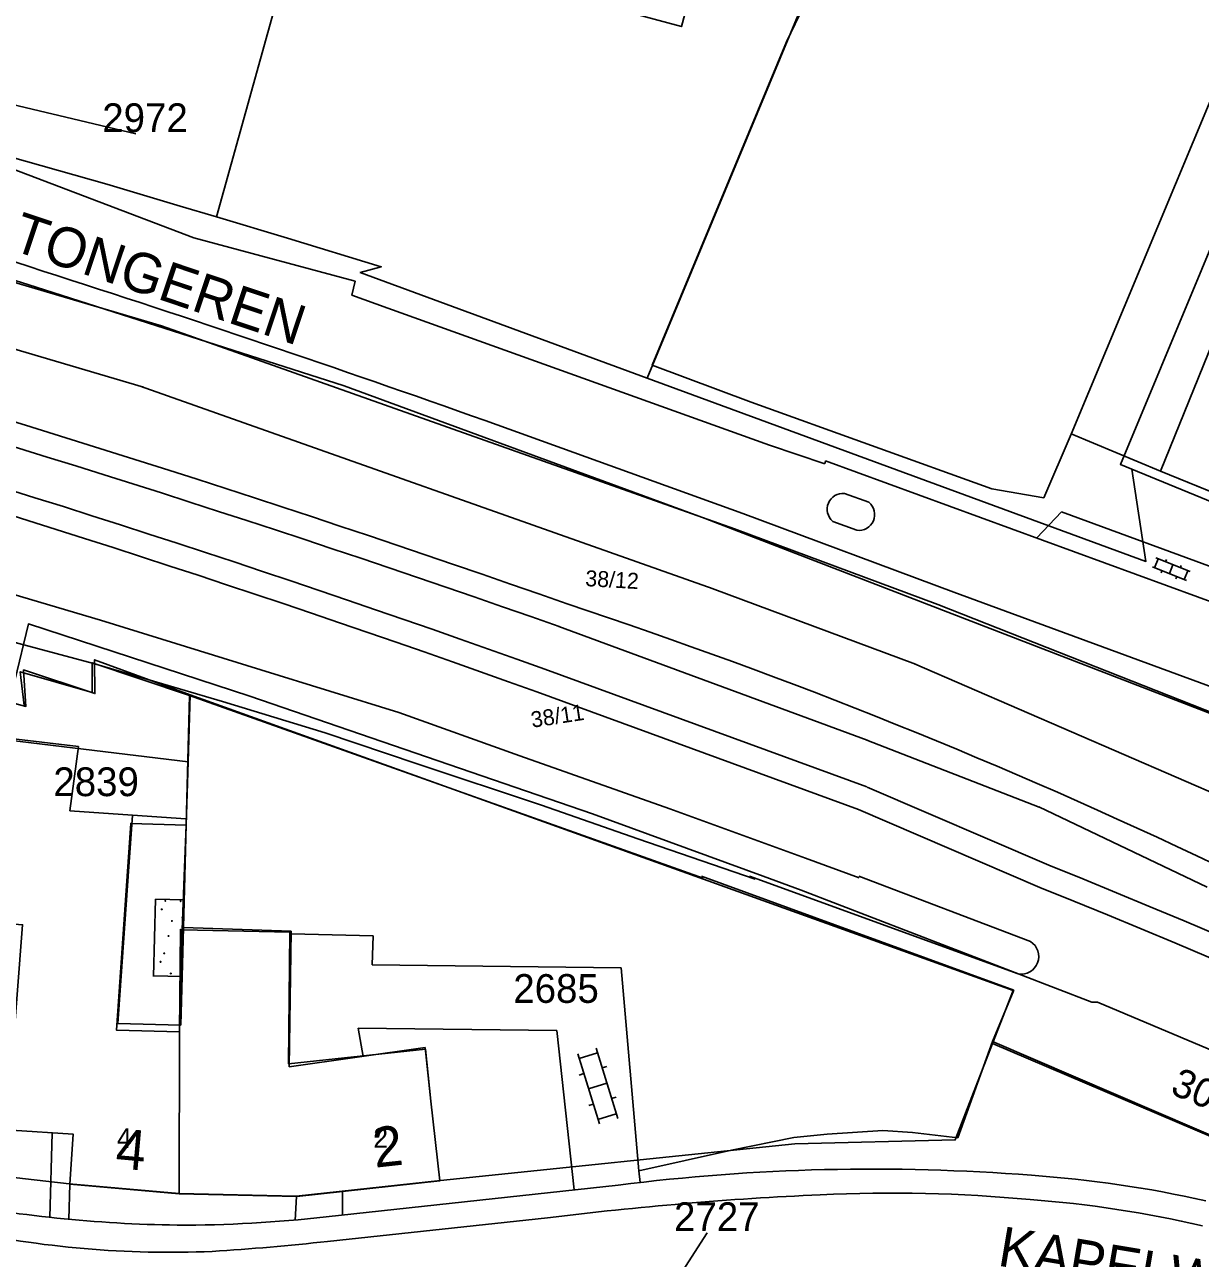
# Model space of a CAD drawing. Extents: x 148816 to 151297, y 399515 to 402500.
# Drawn here: x 149626.7 to 149700.3, y 399976.1 to 400053.3 of the extents above; entities that cross this region are included whole.
import ezdxf

# ---------------------------------------------------------------- set-up
doc = ezdxf.new("R2010")
doc.units = 0
for name, color, linetype in [('B01 Hoofdgebouw  [D] Norm', 7, 'Continuous'), ('B01 Hoofdgebouw  [T] Norm', 7, 'Continuous'), ('B01 hoofgebouw', 7, 'Continuous'), ('B07 Tussenmuur  [D] Norm', 7, 'Continuous'), ('G01 perceelsgrens', 7, 'Continuous'), ('Q01 Spoorrail  [D] Norm', 7, 'Continuous'), ('S02 Open verharding  Norm', 7, 'Continuous'), ('S05 Water  Norm', 7, 'Continuous'), ('T03 Hek raster  [T] Norm', 7, 'Continuous'), ('T04 Haag heg  [D] Gem', 7, 'Continuous'), ('T09 Insteek water  [T] Norm', 7, 'Continuous'), ('V00 Kant verharding algemeen  [T] Norm', 7, 'Continuous'), ('Z01 perceelnummer', 7, 'Continuous'), ('Z02 huisnummer', 7, 'Continuous'), ('Z02 Huisnummer  [Tekst] Norm', 7, 'Continuous'), ('Z06 straatnaam', 7, 'Continuous'), ('Z19 Overige Tekst  [Tekst] Gem', 7, 'Continuous')]:
    doc.layers.add(name, color=color, linetype=linetype)

msp = doc.modelspace()

# ---------------------------------------------------------------- linework, layer by layer
at = {"layer": 'B01 Hoofdgebouw  [D] Norm'}
for p, q in [((149630.091, 400008.118), (149629.557, 400004.103)), ((149629.557, 400004.103), (149633.475, 400003.827)), ((149633.475, 400003.827), (149633.206, 400000)), ((149633.206, 400000), (149632.557, 399990.779)), ((149636.666, 399996.796), (149636.501, 399990.683)), ((149643.41, 399996.563), (149636.666, 399996.796)), ((149643.288, 399988.069), (149643.41, 399996.563)), ((149636.505, 399990.676), (149632.557, 399990.779)), ((149651.8, 399989.272), (149643.288, 399988.069)), ((149652.16, 399985.91), (149651.8, 399989.272))]:
    msp.add_line(p, q, dxfattribs=at)
msp.add_lwpolyline([(149624.83, 400001.37), (149625.861, 400008.615), (149630.091, 400008.118)], dxfattribs=at)
at = {"layer": 'B01 Hoofdgebouw  [T] Norm'}
for p, q in [((149697.82, 400025.37), (149701.11, 400033.43)), ((149707.97, 400021.23), (149697.82, 400025.37)), ((149652.71, 399980.94), (149652.16, 399985.91)), ((149625.9, 399984.1), (149629.76, 399983.86)), ((149629.76, 399983.86), (149629.56, 399980.73)), ((149629.56, 399980.73), (149636.4, 399980.12)), ((149643.76, 399979.96), (149652.71, 399980.94)), ((149636.4, 399980.12), (149643.76, 399979.96))]:
    msp.add_line(p, q, dxfattribs=at)
msp.add_lwpolyline([(149667.836, 400053.193), (149674.892, 400079.331), (149679.233, 400078.145), (149683.189, 400092.8), (149646.178, 400102.807), (149644.351, 400096.05), (149634.717, 400098.655), (149632.644, 400090.902), (149632.76, 400090.87), (149630.76, 400083.56), (149631.24, 400083.43), (149630.52, 400080.82), (149630.04, 400080.95), (149626.76, 400068.98), (149636.53, 400066.31), (149636.68, 400066.78), (149640.92, 400065.61), (149640.8, 400065.1), (149654.51, 400061.38), (149653.39, 400057.093), (149667.836, 400053.193)], dxfattribs=at)
at = {"layer": 'B01 hoofgebouw'}
for points in [[(149669.139, 400058.02), (149667.836, 400053.193), (149653.39, 400057.093), (149654.51, 400061.38), (149640.8, 400065.099), (149640.92, 400065.609), (149636.68, 400066.781), (149636.53, 400066.309), (149626.76, 400068.98), (149630.04, 400080.951), (149630.52, 400080.819), (149631.24, 400083.429), (149630.76, 400083.56), (149632.76, 400090.87), (149637.583, 400089.55)], [(149709.86, 400025.86), (149707.97, 400021.23), (149697.82, 400025.37), (149701.11, 400033.43), (149703.1, 400032.62), (149705.84, 400039.09), (149703.75, 400039.96), (149705.93, 400045.23), (149710.55, 400043.32)], [(149633.132, 400000), (149633.36, 400003.31), (149636.83, 400003.2), (149636.95, 400007.17), (149626.44, 400008.43), (149625.74, 400008.52), (149624.397, 400000)], [(149652.16, 399985.91), (149651.82, 399989.17), (149643.25, 399988.25), (149643.32, 399996.51), (149636.58, 399996.65), (149636.47, 399996.67), (149636.42, 399990.27), (149632.47, 399990.37), (149633.132, 400000)], [(149652.16, 399985.91), (149652.71, 399980.94), (149643.76, 399979.96), (149636.4, 399980.12), (149629.56, 399980.731), (149629.76, 399983.86), (149625.9, 399984.1), (149625.89, 399983.86), (149625.58, 399983.87), (149626.59, 399996.96), (149624.5, 399997.12), (149624.4, 399996.42), (149624.13, 399996.45)]]:
    msp.add_lwpolyline(points, dxfattribs=at)
at = {"layer": 'B07 Tussenmuur  [D] Norm'}
for centre, radius, start, end in [((149677.958, 400022.978), 0.997, 85.39804, 229.43277), ((149677.958, 400022.978), 0.997, 85.39804, 229.43277), ((149678.944, 400022.643), 0.992, 262.3134, 50.71943), ((149678.944, 400022.643), 0.992, 262.3134, 50.71943)]:
    msp.add_arc(centre, radius, start, end, dxfattribs=at)
at = {"layer": 'G01 perceelsgrens'}
for points in [[(149638.729, 400041.284), (149656.845, 400106.356), (149655.006, 400111.508), (149654.359, 400111.132)], [(149665.698, 400031.192), (149693.448, 400097.989)], [(149134.62, 400061.65), (149206.52, 400066.52), (149335.42, 400075.13), (149370.7, 400075.72), (149405.93, 400074.91), (149434.14, 400073.21), (149462.22, 400070.63), (149506.14, 400065.44), (149531.96, 400061.45), (149557.59, 400056.16), (149609.02, 400042.67), (149626.93, 400037.04), (149646.73, 400030.71), (149669.32, 400022.39), (149727.336, 400000)], [(149715.586, 400074.465), (149695.319, 400025.788), (149696.029, 400025.496)], [(149624.68, 400045.359), (149631.861, 400043.332), (149636.455, 400041.95), (149638.729, 400041.284)], [(149638.729, 400041.284), (149643.173, 400039.952), (149649.045, 400038.164), (149647.73, 400037.799), (149665.698, 400031.192)], [(149501.19, 400041.145), (149537.356, 400033.966), (149547.718, 400031.518), (149559.282, 400029.587), (149570.835, 400027.359), (149578.92, 400025.467), (149588.175, 400023.166), (149603.441, 400018.929), (149626.107, 400012.266), (149626.962, 400015.794), (149640.811, 400011.27), (149662.269, 400003.906), (149672.952, 400000)], [(149665.698, 400031.192), (149696.918, 400019.713), (149696.029, 400025.496)], [(149696.029, 400025.496), (149702.686, 400022.757)], [(149626.102, 400010.819), (149626.8, 400010.63), (149626.66, 400012.92), (149631.12, 400011.44), (149631.1, 400013.56), (149637.09, 400011.35)], [(149636.708, 400000), (149636.83, 400003.2), (149636.95, 400007.17), (149637.09, 400011.35)], [(149637.09, 400011.35), (149668.698, 400000)], [(149636.39, 399980.13), (149636.42, 399990.27), (149636.58, 399996.65), (149636.708, 400000)], [(149668.698, 400000), (149688.61, 399992.85), (149687.31, 399989.53)], [(149672.952, 400000), (149675.332, 399999.13), (149693.527, 399992.123), (149693.888, 399992.111), (149716.001, 399982.797), (149751.173, 399967.18)], [(149636.39, 399980.13), (149643.72, 399979.98), (149652.75, 399980.95), (149674.94, 399983.24), (149684.98, 399983.49), (149687.31, 399989.53)], [(149687.31, 399989.53), (149736.79, 399968.45), (149743.6, 399966.54), (149751.173, 399967.18)], [(149622.02, 399981.61), (149629.5, 399980.75), (149636.39, 399980.13)]]:
    msp.add_lwpolyline(points, dxfattribs=at)
at = {"layer": 'Q01 Spoorrail  [D] Norm'}
for p, q in [((149679.46, 400008.512), (149660.16, 400015.642)), ((149659.294, 400012.958), (149679.434, 400005.598)), ((149658.78, 400011.55), (149678.92, 400004.19)), ((149679.437, 400008.521), (149690.232, 400004.331)), ((149690.841, 400000.695), (149679.461, 400005.588)), ((149690.277, 399999.305), (149678.92, 400004.19)), ((149690.214, 400004.338), (149700.757, 399999.308))]:
    msp.add_line(p, q, dxfattribs=at)
for centre, radius, start, end in [((149365.779, 399180.187), 887.303, 70.588125, 78.352931), ((149365.779, 399180.187), 885.803, 70.588125, 78.352931), ((149377.627, 399228.625), 833.377, 70.246469, 78.478792), ((149377.627, 399228.625), 831.877, 70.246469, 78.478792), ((149551.065, 399685.913), 348.808, 64.48078, 71.68418), ((149374.899, 399222.566), 839.824, 47.976611, 67.901486), ((149374.899, 399222.566), 838.324, 47.976611, 67.901486)]:
    msp.add_arc(centre, radius, start, end, dxfattribs=at)
at = {"layer": 'S02 Open verharding  Norm'}
for p, q in [((149697.456, 400019.318), (149697.68, 400019.875)), ((149697.541, 400019.931), (149699.675, 400019.074)), ((149698.2, 400019.828), (149698.144, 400019.689)), ((149697.317, 400019.374), (149699.451, 400018.517)), ((149697.92, 400019.132), (149697.864, 400018.993)), ((149698.608, 400019.502), (149698.384, 400018.946)), ((149699.128, 400019.455), (149699.072, 400019.316)), ((149699.312, 400018.573), (149699.536, 400019.13)), ((149698.848, 400018.759), (149698.792, 400018.62)), ((149662.701, 399984.491), (149661.348, 399988.888)), ((149662.583, 399988.954), (149661.436, 399988.601)), ((149663.848, 399984.844), (149662.495, 399989.241)), ((149662.877, 399987.998), (149663.164, 399988.087)), ((149661.444, 399987.557), (149661.73, 399987.645)), ((149662.025, 399986.689), (149663.171, 399987.043)), ((149662.032, 399985.645), (149662.319, 399985.734)), ((149663.466, 399986.087), (149663.752, 399986.175)), ((149663.76, 399985.131), (149662.613, 399984.778))]:
    msp.add_line(p, q, dxfattribs=at)
at = {"layer": 'S05 Water  Norm'}
for centre in [(149635.533, 399998.463), (149636.487, 399998.447), (149635.304, 399997.928), (149635.945, 399997.199), (149636.602, 399997.41), (149635.731, 399996.261), (149636.602, 399996.373), (149635.461, 399995.177), (149636.569, 399995.515), (149635.231, 399994.642), (149636.529, 399994.124), (149635.872, 399993.914)]:
    msp.add_circle(centre, 0.025, dxfattribs=at)
at = {"layer": 'T03 Hek raster  [T] Norm'}
msp.add_lwpolyline([(149752.218, 399969.183), (149750.792, 399970.054), (149744.644, 399966.31), (149736.663, 399968.567), (149726.28, 399973.022), (149715.897, 399977.476), (149702.603, 399983.085), (149687.301, 399989.658)], dxfattribs=at)
at = {"layer": 'T04 Haag heg  [D] Gem'}
for p, q in [((149696.195, 400097.041), (149674.407, 400052.247)), ((149713.887, 400079.62), (149692.227, 400027.674)), ((149674.407, 400052.247), (149666.012, 400032.008)), ((149666.012, 400032.008), (149672.204, 400029.687)), ((149672.204, 400029.687), (149687.266, 400024.26)), ((149690.521, 400023.684), (149692.227, 400027.674)), ((149692.237, 400027.698), (149697.82, 400025.37)), ((149687.266, 400024.26), (149690.521, 400023.684)), ((149637.048, 400011.315), (149636.748, 400000)), ((149636.666, 399996.796), (149636.748, 400000)), ((149669.088, 400000), (149688.646, 399992.864)), ((149688.646, 399992.864), (149687.301, 399989.658)), ((149687.301, 399989.658), (149685.144, 399983.629)), ((149680.443, 399984.083), (149676.961, 399983.851)), ((149682.298, 399983.957), (149680.443, 399984.083)), ((149674.878, 399983.646), (149670.965, 399982.854)), ((149676.961, 399983.851), (149674.878, 399983.646)), ((149685.144, 399983.629), (149682.298, 399983.957)), ((149670.965, 399982.854), (149665.171, 399981.552))]:
    msp.add_line(p, q, dxfattribs=at)
for points in [[(149626.69, 400010.694), (149626.452, 400012.807), (149630.94, 400011.499), (149630.96, 400013.368), (149637.048, 400011.315)], [(149669.201, 399999.883), (149637.048, 400011.315)]]:
    msp.add_lwpolyline(points, dxfattribs=at)
at = {"layer": 'T09 Insteek water  [T] Norm'}
for p, q in [((149605.76, 400043.18), (149635.3, 400034.46)), ((149604.628, 400039.344), (149634.168, 400030.624)), ((149635.3, 400034.46), (149671.16, 400021.76)), ((149633.965, 400030.689), (149669.825, 400017.989)), ((149683.89, 400017.02), (149671.16, 400021.76)), ((149682.494, 400013.271), (149669.764, 400018.011)), ((149683.89, 400017.02), (149717.56, 400003.71)), ((149682.419, 400013.3), (149725.99, 399994.44)), ((149672.094, 400000), (149688.925, 399993.882)), ((149678.939, 400000), (149689.686, 399995.917))]:
    msp.add_line(p, q, dxfattribs=at)
for points in [[(149678.972, 399999.899), (149675.595, 400001.136), (149667.113, 400004.217), (149657.717, 400007.55), (149650.15, 400010.251), (149641.517, 400012.926), (149631.462, 400016.029), (149622.092, 400018.803), (149613.738, 400021.301), (149603.099, 400024.479), (149594.162, 400027.052), (149588.881, 400028.463), (149577.379, 400031.463), (149562.933, 400035.092), (149556.255, 400036.603), (149535.285, 400041.058), (149535.285, 400041.058)], [(149672.45, 399999.813), (149665.111, 400002.337), (149659.068, 400004.458), (149651.297, 400007.032), (149645.533, 400008.975), (149639.109, 400010.943), (149631.035, 400013.314), (149625.17, 400014.877), (149616.334, 400017.146), (149606.407, 400019.59), (149596.912, 400021.755), (149590.895, 400023.09), (149586.731, 400024.022), (149576.423, 400026.668), (149565.734, 400029.415), (149551.566, 400032.892), (149540.929, 400035.157), (149540.929, 400035.157)]]:
    msp.add_lwpolyline(points, dxfattribs=at)
msp.add_arc((149689.097, 399994.978), 1.109, 261.10319, 57.88965, dxfattribs=at)
at = {"layer": 'V00 Kant verharding algemeen  [T] Norm'}
for p, q in [((149625.46, 400044.48), (149637.32, 400039.96)), ((149637.32, 400039.96), (149647.41, 400037.26)), ((149647.41, 400037.26), (149647.21, 400036.39)), ((149647.21, 400036.39), (149649.46, 400035.57)), ((149649.46, 400035.57), (149673.35, 400027)), ((149671.69, 400022.72), (149655.55, 400028.53)), ((149676.82, 400025.82), (149673.35, 400027)), ((149676.86, 400026), (149676.82, 400025.82)), ((149741.99, 400002.18), (149676.86, 400026)), ((149679.572, 400023.411), (149678.038, 400023.972)), ((149671.69, 400022.72), (149684.88, 400017.79)), ((149691.62, 400022.82), (149690.08, 400021.19)), ((149741.67, 400004.45), (149691.62, 400022.82)), ((149677.31, 400022.221), (149678.811, 400021.66)), ((149684.88, 400017.79), (149721.39, 400004.35)), ((149633.475, 400003.827), (149636.815, 400003.592)), ((149634.91, 399998.569), (149634.784, 399993.724)), ((149636.709, 399998.522), (149634.91, 399998.569)), ((149643.408, 399996.403), (149648.543, 399996.263)), ((149648.543, 399996.263), (149648.468, 399994.457)), ((149648.468, 399994.457), (149664.071, 399994.267)), ((149664.071, 399994.267), (149665.171, 399981.552)), ((149636.584, 399993.724), (149634.785, 399993.771)), ((149647.908, 399988.722), (149647.606, 399990.489)), ((149647.606, 399990.489), (149660.033, 399990.347)), ((149660.033, 399990.347), (149661.118, 399980.362)), ((149628.292, 399978.645), (149628.436, 399983.942)), ((149665.171, 399981.552), (149665.262, 399980.829)), ((149629.56, 399980.73), (149629.486, 399978.52)), ((149663.87, 399980.66), (149645.59, 399978.68)), ((149646.621, 399980.273), (149646.622, 399978.792)), ((149643.744, 399979.96), (149643.658, 399978.48)), ((149659.46, 399978.61), (149645.69, 399977.14))]:
    msp.add_line(p, q, dxfattribs=at)
for centre, radius, start, end in [((149452.844, 399508.369), 557.697, 71.70942, 77.61595), ((149339.396, 399139.187), 943.866, 70.430117, 72.203919), ((149679.822, 399855.254), 126.416, 85.49557, 97.24913), ((149684.751, 399909.199), 72.254, 77.28056, 86.03302), ((149637.397, 400062.197), 84.044, 258.93443, 269.23245), ((149685.941, 399768.061), 212.207, 92.54192, 97.16865), ((149680.982, 399887.13), 93.036, 84.64158, 92.74261), ((149684.327, 399908.289), 71.671, 76.99091, 85.72431), ((149636.518, 400057.497), 79.338, 269.82163, 276.56595), ((149635.858, 400039.699), 63.24, 257.81454, 272.36405), ((149628.971, 400127.827), 151.612, 273.5911, 276.33127)]:
    msp.add_arc(centre, radius, start, end, dxfattribs=at)
at = {"layer": 'Z01 perceelnummer'}
for points in [[(149633.679, 400046.489), (149623.235, 400048.955)], [(149669.44, 399977.687), (149663.825, 399968.955)]]:
    msp.add_lwpolyline(points, dxfattribs=at)

# ---------------------------------------------------------------- texts
for s, p in [('2972', (149631.582, 400046.589)), ('2839', (149628.521, 400005.016)), ('2685', (149657.312, 399992.073)), ('2727', (149667.374, 399977.787))]:
    msp.add_text(s, height=1.8, dxfattribs=at).set_placement(p)
msp.add_text('3051', height=1.8, rotation=336.95207, dxfattribs=at).set_placement((149698.366, 399986.416))
at = {"layer": 'Z02 huisnummer'}
for s, rotation, p in [('4', 354.89376, (149632.357, 399981.735)), ('2', 6.25793, (149648.654, 399981.752))]:
    msp.add_text(s, height=2.5, rotation=rotation, dxfattribs=at).set_placement(p)
at = {"layer": 'Z02 Huisnummer  [Tekst] Norm'}
for s, p in [('4', (149632.5, 399982.98)), ('2', (149648.55, 399983))]:
    msp.add_text(s, height=1.249, dxfattribs=at).set_placement(p)
at = {"layer": 'Z06 straatnaam'}
for s, rotation, p in [('TONGEREN', 341.45633, (149625.8, 400039.246)), ('KAPELWEG', 350.49999, (149687.57, 399975.635))]:
    msp.add_text(s, height=2.5, rotation=rotation, dxfattribs=at).set_placement(p)
at = {"layer": 'Z19 Overige Tekst  [Tekst] Gem'}
for s, rotation, p in [('38/12', 356.73526, (149661.8, 400018.17)), ('38/11', 8.63236, (149658.495, 400009.295))]:
    msp.add_text(s, height=1, rotation=rotation, dxfattribs=at).set_placement(p)

doc.saveas('drawing.dxf')
